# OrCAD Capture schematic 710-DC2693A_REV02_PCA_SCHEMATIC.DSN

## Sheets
1 LTC5556 - PAGE2: size Custom; note: DUAL PROGRAMMABLE GAIN MIXER
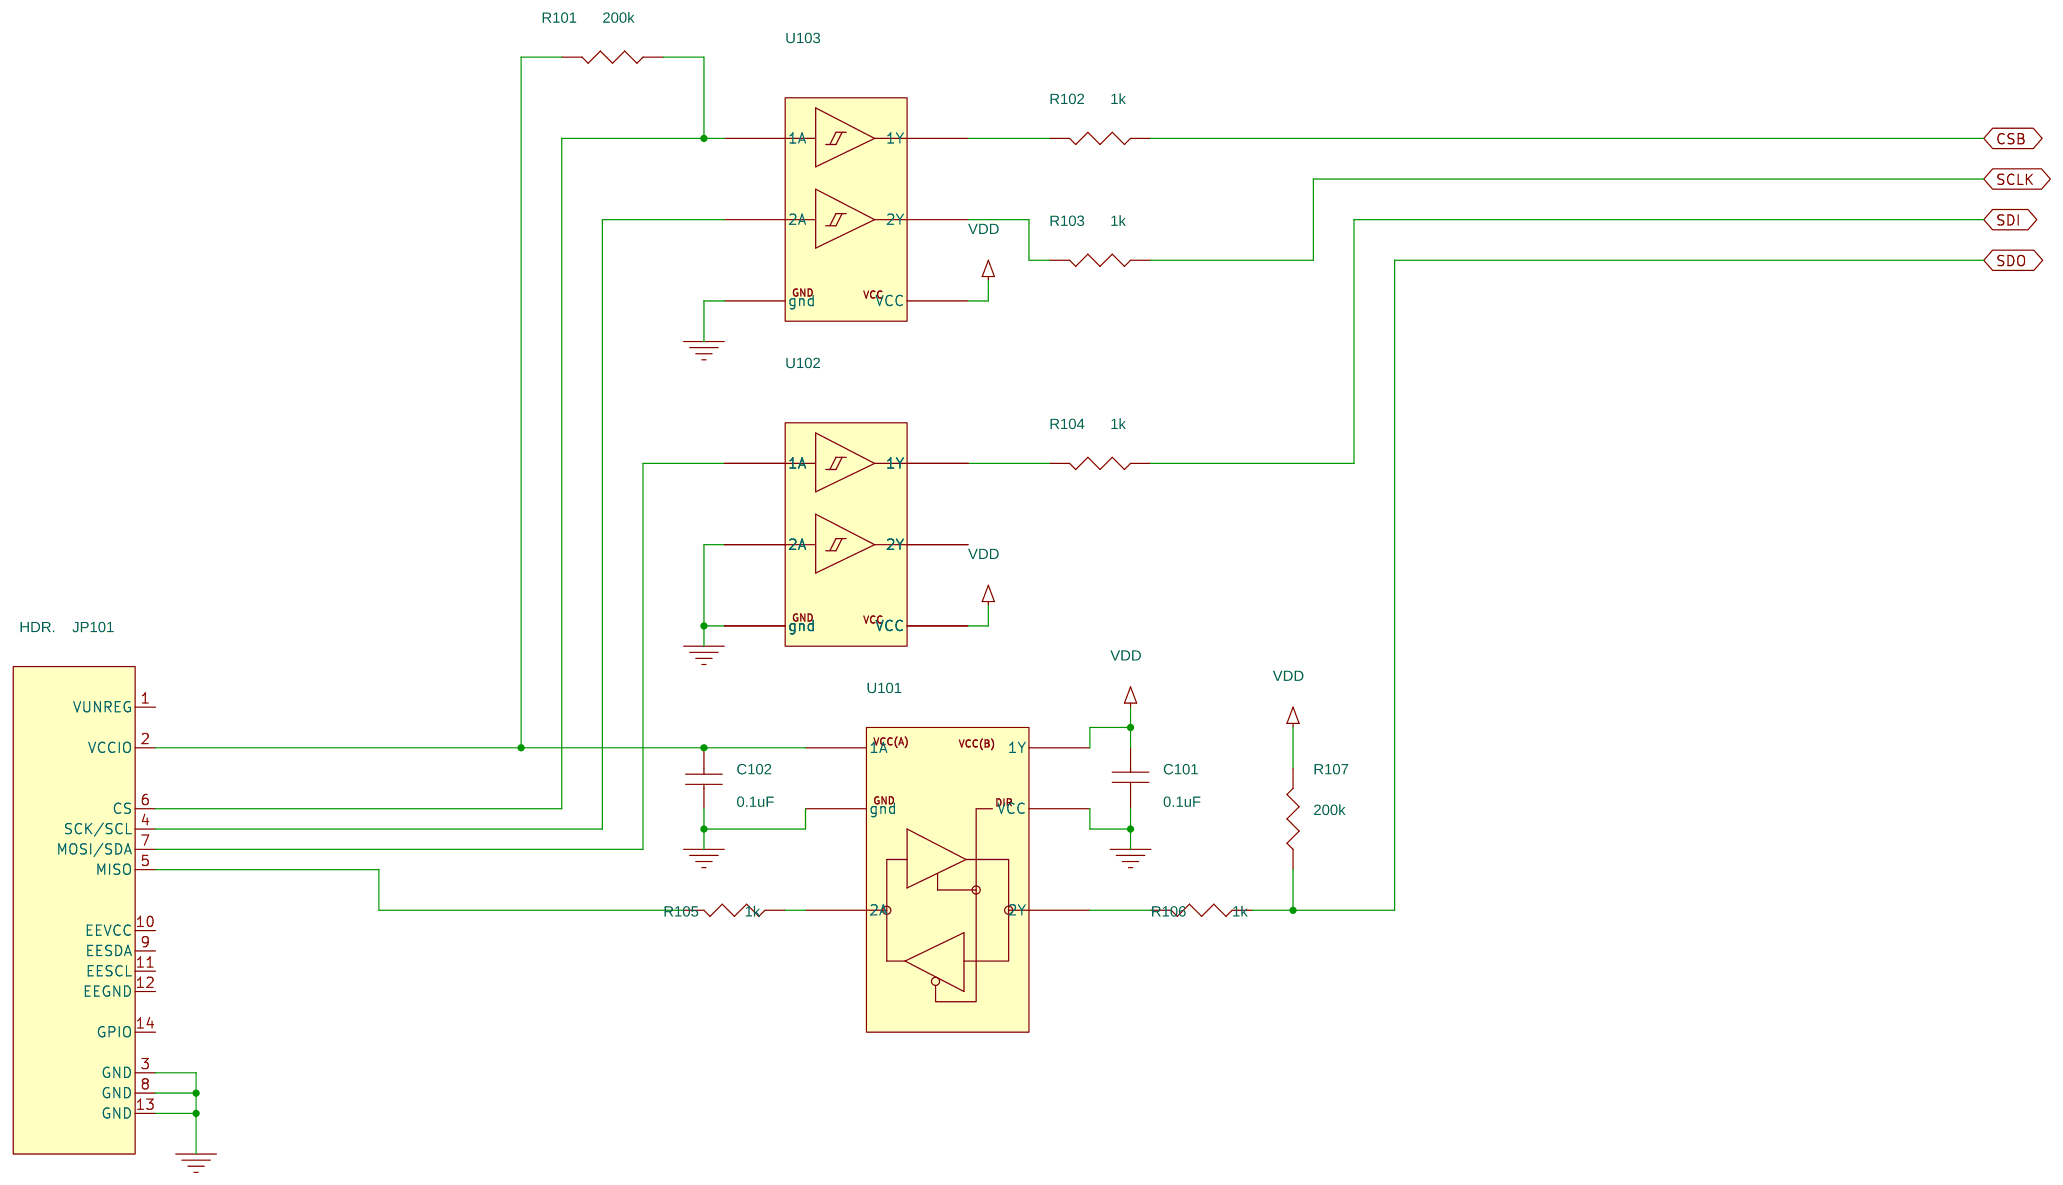
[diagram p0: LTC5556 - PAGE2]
2 LTC5556 - PAGE 1: size Custom
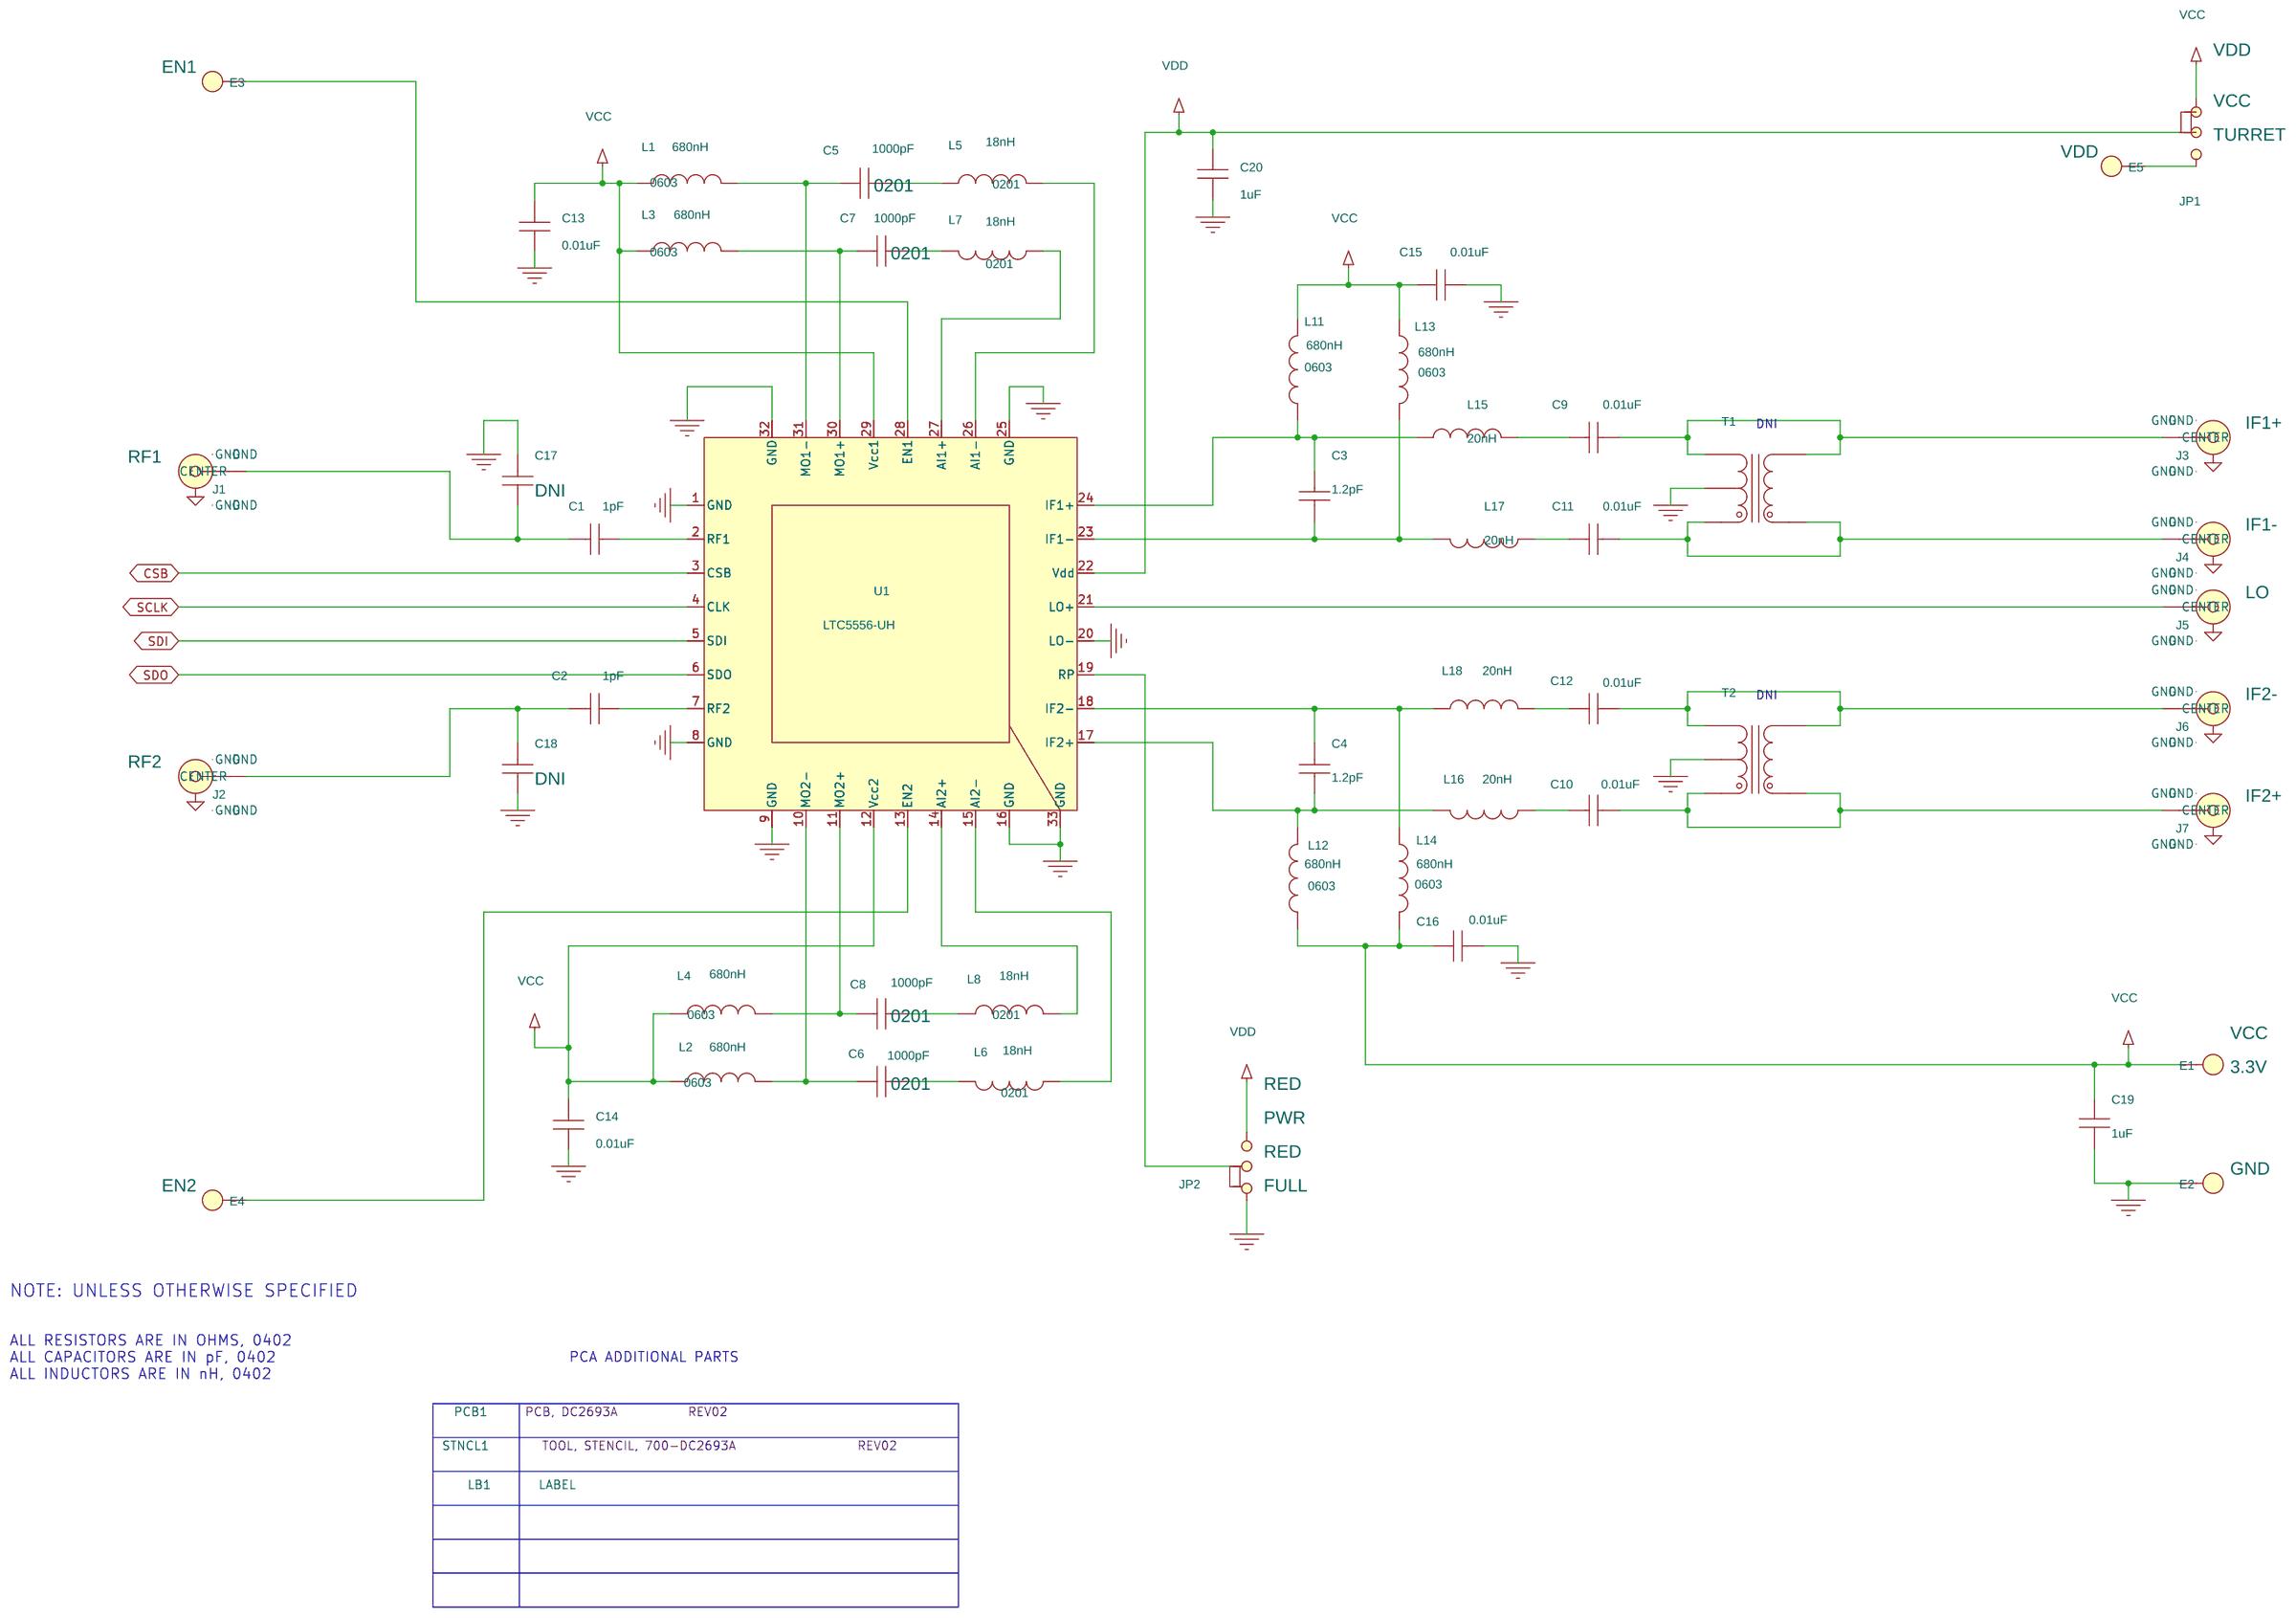
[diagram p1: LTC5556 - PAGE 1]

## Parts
sheet LTC5556 - PAGE2
C101  0.1uF  [CC0402N]
C102  0.1uF  [CC0402N]
JP101  HDR.  [HD2X7-079-MOLEX]
R101  200k  [CR0402N]
R102  1k  [CR0402N]
R103  1k  [CR0402N]
R104  1k  [CR0402N]
R105  1k  [CR0402N]
R106  1k  [CR0402N]
R107  200k  [CR0402N]
U101  74LVC1T45GW  [SOT363-6N]
U102  NC7WZ17P6X  [SC-70(6LEAD)\VISHAY]
U103  NC7WZ17P6X  [SC-70(6LEAD)\VISHAY]
sheet LTC5556 - PAGE 1
C1  1pF  [CC0402N]
C2  1pF  [CC0402N]
C3  1.2pF  [CC0402N]
C4  1.2pF  [CC0402N]
C5  1000pF  [CC0201N]
C6  1000pF  [CC0201N]
C7  1000pF  [CC0201N]
C8  1000pF  [CC0201N]
C9  0.01uF  [CC0402N]
C10  0.01uF  [CC0402N]
C11  0.01uF  [CC0402N]
C12  0.01uF  [CC0402N]
C13  0.01uF  [CC0402N]
C14  0.01uF  [CC0402N]
C15  0.01uF  [CC0402N]
C16  0.01uF  [CC0402N]
C17  OPT  [CC0402N]
C18  OPT  [CC0402N]
C19  1uF  [CC0603N]
C20  1uF  [CC0603N]
E1  TEST POINT  [MILLMAX2308]
E2  TEST POINT  [MILLMAX2308]
E3  TEST POINT  [MILLMAX2308]
E4  TEST POINT  [MILLMAX2308]
E5  TEST POINT  [MILLMAX2308]
J1  SMA  [EMERSON_142-0701-851]
J2  SMA  [EMERSON_142-0701-851]
J3  SMA  [EMERSON_142-0701-851]
J4  SMA  [EMERSON_142-0701-851]
J5  SMA  [EMERSON_142-0701-851]
J6  SMA  [EMERSON_142-0701-851]
J7  SMA  [EMERSON_142-0701-851]
JP1  HDR.  [HD1X3-079]
JP2  HDR.  [HD1X3-079]
L1  680nH  [COILCRAFT-0603CS]
L2  680nH  [COILCRAFT-0603CS]
L3  680nH  [COILCRAFT-0603CS]
L4  680nH  [COILCRAFT-0603CS]
L5  18nH  [IND0201N]
L6  18nH  [IND0201N]
L7  18nH  [IND0201N]
L8  18nH  [IND0201N]
L11  680nH  [COILCRAFT-0603CS]
L12  680nH  [COILCRAFT-0603CS]
L13  680nH  [COILCRAFT-0603CS]
L14  680nH  [COILCRAFT-0603CS]
L15  20nH  [IND0402N]
L16  20nH  [IND0402N]
L17  20nH  [IND0402N]
L18  20nH  [IND0402N]
LB1  LABEL  [895-0154_REV01]
PCB1  PCB, DC2693A
STNCL1  TOOL, STENCIL, 700-DC2693A
T1  TRANS-TC4-1W-7ALN+  [TRANS-TC4-1W-7ALN]
T2  TRANS-TC4-1W-7ALN+  [TRANS-TC4-1W-7ALN]
U1  LTC5556-UH  [LTC-QFN-32-1693]
XJP1  SHUNT
XJP2  SHUNT

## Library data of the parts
C101 C102 = CAP: CAP.,0.1uF,X7R,50V,10%,0402; CLASS: DISCRETE; Dielectric Type: X7R; FPLIST: CC0402N,CC0402L,CC0402M; Manufacturer: MURATA; Manufacturer PN: GRM155R71H104KE14D; PART_NUMBER: 150-3240; Package Size: 0402; Package Type: SMD; Rated Voltage: 50V; Tolerance: 10%
JP101 = CONN_2X7_.079_MOLEX_RIBBON_A: CONN.,HDR.,MALE,2x7,2mm,THT, VERT,SHROUDED; CLASS: IO; Manufacturer: MOLEX; Manufacturer PN: 87831-1420; PART_NUMBER: 250-0403
R101 R107 = RES: RES.,200k OHMS,1%,1/16W,0402; CLASS: DISCRETE; FPLIST: CR0402N,CR0402L,CR0402M; Manufacturer: PANASONIC; Manufacturer PN: ERJ2RKF2003X; PART_NUMBER: 100-0329; Package Size: 0402; Rated Power: 1/16W; Temperature Coefficient: 100ppm/C; Tolerance: 1%
R102-R106 = RES: RES.,1k OHM,1%,1/16W,0402; CLASS: DISCRETE; FPLIST: CR0402N,CR0402L,CR0402M; Manufacturer: VISHAY; Manufacturer PN: CRCW04021K00FKED; PART_NUMBER: 100-2456; Package Size: 0402; Rated Power: 1/16W; Temperature Coefficient: 100ppm/C; Tolerance: 1%
U101 = 74LVC1T45_v2: IC,Dual Supply Transceiver,SOT363-6 (SC-88),Single Bit, 3-State Outputs; CLASS: IC; Manufacturer: NEXPERIA; Manufacturer PN: 74LVC1T45GW,125; PART_NUMBER: 280-8080; Package Type: SOT363-6 (SC-88)
U102 U103 = NC7WZ17: IC,TinyLogic UHS Dual Buffer,SC70-6; CLASS: IC; Manufacturer: FAIRCHILD SEMI.; PART_NUMBER: 280-0294; Package Type: SC70-6
C1 C2 = CAP: CAP.,1pF,C0G,50V,+/-0.05pF,0402,High Q; CLASS: DISCRETE; Dielectric Type: C0G; FPLIST: CC0402N,CC0402L,CC0402M; Manufacturer: MURATA; Manufacturer PN: GJM1555C1H1R0WB01D; PART_NUMBER: 150-2023; Package Size: 0402; Rated Voltage: 50V; Tolerance: +/-0.05pF; UserField01: High Q
C3 C4 = CAP: CAP.,1.2pF,C0G,50V,+/-0.05pF,0402,HIGH Q; CLASS: DISCRETE; Dielectric Type: C0G; FPLIST: CC0402N,CC0402L,CC0402M; Manufacturer: MURATA; Manufacturer PN: GJM1555C1H1R2WB01D; PART_NUMBER: 150-2024; Package Size: 0402; Rated Voltage: 50V; Tolerance: +/-0.05pF; UserField01: High Q
C5-C8 = CAP: CAP.,1000pF,X7R,50V,10%,0201; CLASS: DISCRETE; Dielectric Type: X7R; FPLIST: CC0201N,CC0201L,CC0201M; Manufacturer: MURATA; Manufacturer PN: GRM033R71H102KA12D; PART_NUMBER: 150-2256; Package Size: 0201; Rated Voltage: 50V; Tolerance: 10%
C9-C16 = CAP: CAP.,0.01uF,X7R,50V,10%,0402; CLASS: DISCRETE; Dielectric Type: X7R; FPLIST: CC0402N,CC0402L,CC0402M; Manufacturer: KEMET; Manufacturer PN: C0402C103K5RAC7867; PART_NUMBER: 150-0041; Package Size: 0402; Rated Voltage: 50V; Tolerance: 10%
C17 C18 = CAP: CAP., OPTION, 0402; 1: DNI; CLASS: DISCRETE; FPLIST: CC0402N,CC0402L,CC0402M; PART_NUMBER: 150-3148; Package Size: 0402; Package Type: SMD
C19 C20 = CAP: CAP.,1uF,X7R,16V,10%,0603; CLASS: DISCRETE; Dielectric Type: X7R; FPLIST: CC0603N,CC0603L,CC0603M; Manufacturer: MURATA; Manufacturer PN: GRM188R71C105KA12D; PART_NUMBER: 150-0179; Package Size: 0603; Rated Voltage: 16V; Tolerance: 10%
E1 = TEST_POINT_.156_MILL-MAX_2308: TEST POINT,TURRET,0.064",MTG. HOLE; 1: VCC; 2: 3.3V; CLASS: IO; Manufacturer: MILL-MAX; Manufacturer PN: 2308-2-00-80-00-00-07-0; PART_NUMBER: 260-0004
E2 = TEST_POINT_.156_MILL-MAX_2308: TEST POINT,TURRET,0.064",MTG. HOLE; 1: GND; CLASS: IO; Manufacturer: MILL-MAX; Manufacturer PN: 2308-2-00-80-00-00-07-0; PART_NUMBER: 260-0004
E3 = TEST_POINT_.156_MILL-MAX_2308: TEST POINT,TURRET,0.064",MTG. HOLE; 1: EN1; CLASS: IO; Manufacturer: MILL-MAX; Manufacturer PN: 2308-2-00-80-00-00-07-0; PART_NUMBER: 260-0004
E4 = TEST_POINT_.156_MILL-MAX_2308: TEST POINT,TURRET,0.064",MTG. HOLE; 1: EN2; CLASS: IO; Manufacturer: MILL-MAX; Manufacturer PN: 2308-2-00-80-00-00-07-0; PART_NUMBER: 260-0004
E5 = TEST_POINT_.156_MILL-MAX_2308: TEST POINT,TURRET,0.064",MTG. HOLE; 1: VDD; CLASS: IO; Manufacturer: MILL-MAX; Manufacturer PN: 2308-2-00-80-00-00-07-0; PART_NUMBER: 260-0004
J1 = CONN_SMA_5PIN: CONN.,SMA,JACK, RCPT,END LAUNCH, STR,50 OHMS; 1: RF1; CLASS: IO; FPLIST: EMERSON_142-0701-851,SMA-CINCH-142-0761-881_142-0701-851; Manufacturer: CINCH/ BEL; Manufacturer PN: 142-0701-851; PART_NUMBER: 250-0446
J2 = CONN_SMA_5PIN: CONN.,SMA,JACK, RCPT,END LAUNCH, STR,50 OHMS; 1: RF2; CLASS: IO; FPLIST: EMERSON_142-0701-851,SMA-CINCH-142-0761-881_142-0701-851; Manufacturer: CINCH/ BEL; Manufacturer PN: 142-0701-851; PART_NUMBER: 250-0446
J3 = CONN_SMA_5PIN: CONN.,SMA,JACK, RCPT,END LAUNCH, STR,50 OHMS; 1: IF1+; CLASS: IO; FPLIST: EMERSON_142-0701-851,SMA-CINCH-142-0761-881_142-0701-851; Manufacturer: CINCH/ BEL; Manufacturer PN: 142-0701-851; PART_NUMBER: 250-0446
J4 = CONN_SMA_5PIN: CONN.,SMA,JACK, RCPT,END LAUNCH, STR,50 OHMS; 1: IF1-; CLASS: IO; FPLIST: EMERSON_142-0701-851,SMA-CINCH-142-0761-881_142-0701-851; Manufacturer: CINCH/ BEL; Manufacturer PN: 142-0701-851; PART_NUMBER: 250-0446
J5 = CONN_SMA_5PIN: CONN.,SMA,JACK, RCPT,END LAUNCH, STR,50 OHMS; 1: LO; CLASS: IO; FPLIST: EMERSON_142-0701-851,SMA-CINCH-142-0761-881_142-0701-851; Manufacturer: CINCH/ BEL; Manufacturer PN: 142-0701-851; PART_NUMBER: 250-0446
J6 = CONN_SMA_5PIN: CONN.,SMA,JACK, RCPT,END LAUNCH, STR,50 OHMS; 1: IF2-; CLASS: IO; FPLIST: EMERSON_142-0701-851,SMA-CINCH-142-0761-881_142-0701-851; Manufacturer: CINCH/ BEL; Manufacturer PN: 142-0701-851; PART_NUMBER: 250-0446
J7 = CONN_SMA_5PIN: CONN.,SMA,JACK, RCPT,END LAUNCH, STR,50 OHMS; 1: IF2+; CLASS: IO; FPLIST: EMERSON_142-0701-851,SMA-CINCH-142-0761-881_142-0701-851; Manufacturer: CINCH/ BEL; Manufacturer PN: 142-0701-851; PART_NUMBER: 250-0446
JP1 = HDR3X1_A: CONN.,HDR.,MALE,1x3,2mm,THT, STR; 1: VDD; 2: VCC; 3: TURRET; CLASS: IO; FPLIST: JP3X1/079,HD1X3-079; Manufacturer: SAMTEC; Manufacturer PN: TMM-103-02-L-S; PART_NUMBER: 250-0422
JP2 = HDR3X1_A: CONN.,HDR.,MALE,1x3,2mm,THT, STR; 1: RED; 2: PWR; 3: RED; 4: FULL; CLASS: IO; FPLIST: JP3X1/079,HD1X3-079; Manufacturer: SAMTEC; Manufacturer PN: TMM-103-02-L-S; PART_NUMBER: 250-0422
L1-L4 L11-L14 = IND: IND.,680nH,RF, FERRITE,5%,0603; CLASS: DISCRETE; Manufacturer: COILCRAFT; Manufacturer PN: 0603AF-681XJEU; PART_NUMBER: 200-0286; Package Size: 0603; Tolerance: 5%
L5-L8 = IND: IND.,18nH,FILM,3%,0201,HIGH Q; CLASS: DISCRETE; Manufacturer: MURATA; Manufacturer PN: LQP03HQ18NH02D; PART_NUMBER: 200-0534; Package Size: 0201; Tolerance: 3%
L15-L18 = IND: IND.,20nH,CER.,2%,0402,HIGH Q; CLASS: DISCRETE; FPLIST: IND0402N,IND0402L,IND0402M; Manufacturer: COILCRAFT; Manufacturer PN: 0402HP-20NXGLU; PART_NUMBER: 200-0536; Package Size: 0402; Tolerance: 2%
LB1 = BLANK_LABEL: LABEL SPEC, DEMO BOARD SERIAL NUMBER; Manufacturer: BRADY; Manufacturer PN: THT-96-717-10; PART_NUMBER: 895-0154
PCB1 = BLANK_PCB_PART: BOM Notes: REV02; CLASS: DISCRETE; Manufacturer: ALLTEK CIRCUITS INC.; Manufacturer PN: 600-DC2693A; PART_NUMBER: 600-DC2693A
STNCL1 = BLANK_STENCIL_PART: BOM Notes: REV02; CLASS: DISCRETE; Manufacturer: LINEAR TECH.; Manufacturer PN: 830-DC2693A; PART_NUMBER: 830-DC2693A
T1 T2 = TRANS-TC4-1W-7ALN+: XFMR,RF,CASE STYLE: AT224-1, 5 to 500 MHz; BOM Notes: NO STUFF; CLASS: DISCRETE; Manufacturer: MINI-CIRCUITS; Manufacturer PN: TC4-1W-7ALN+; PART_NUMBER: 410-0101
U1 = LTC5556-UH: IC,Dual PGM Gain Downcvrtg Mixer,QFN-32,3GHz to 7GHz Wideband IF; CLASS: IC; Manufacturer: LINEAR TECH.; Manufacturer PN: LTC5556IUH#PBF; PART_NUMBER: LTC5556IUH#PBF; Package Type: QFN-32
XJP1 XJP2 = SHUNT_2MM_B: CONN.,SHUNT,FEMALE,2-POS,2mm; CLASS: IO; Manufacturer: SAMTEC; Manufacturer PN: 2SN-BK-G; PART_NUMBER: 250-0419

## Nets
GND: C13.1 C14.1 C15.2 C16.2 C17.2 C18.1 C19.2 C20.2 C101.2 C102.1 E2.1(A) J1.2(GND) J1.3(GND) J1.4(GND) J1.5(GND) J2.2(GND) J2.3(GND) J2.4(GND) J2.5(GND) J3.2(GND) J3.3(GND) J3.4(GND) J3.5(GND) J4.2(GND) J4.3(GND) J4.4(GND) J4.5(GND) J5.2(GND) J5.3(GND) J5.4(GND) J5.5(GND) J6.2(GND) J6.3(GND) J6.4(GND) J6.5(GND) J7.2(GND) J7.3(GND) J7.4(GND) J7.5(GND) JP2.3 JP101.3(GND) JP101.8(GND) JP101.13(GND) T1.2 T2.2 U1.1(GND) U1.8(GND) U1.9(GND) U1.16(GND) U1.20(LO-) U1.25(GND) U1.32(GND) U1.33(GND) U101.2(gnd) U101.5(VCC) U102.2(gnd) U102.3(2A) U103.2(gnd)
VCC: C13.2 C14.2 C15.1 C16.1 C19.1 E1.1(A) JP1.1 L1.1 L2.1 L3.1 L4.1 L11.2 L12.1 L13.2 L14.1 U1.12(Vcc2) U1.29(Vcc1)
VDD: C20.1 C101.1 JP1.2 JP2.1 R107.1 U1.22(Vdd) U101.6(1Y) U102.5(VCC) U103.5(VCC)
CSB: R102.2 U1.3(CSB)
SCLK: R103.2 U1.4(CLK)
SDI: R104.2 U1.5(SDI)
SDO: R106.2 R107.2 U1.6(SDO)
N40757: J5.1(CENTER) U1.21(LO+)
N40785: C1.1 U1.2(RF1)
N40789: C2.1 U1.7(RF2)
N40837: C11.2 J4.1(CENTER) T1.1 T1.6
N40897: C4.2 L14.2 L18.1 U1.18(IF2-)
N40905: C4.1 L12.2 L16.2 U1.17(IF2+)
N40921: L8.2 U1.14(AI2+)
N40937: L6.1 U1.15(AI2-)
N41001: C3.1 L11.1 L15.1 U1.24(IF1+)
N41009: C3.2 L13.1 L17.2 U1.23(IF1-)
N41021: JP2.2 U1.19(RP)
N41085: C2.2 C18.2 J2.1(CENTER)
N41089: C1.2 C17.1 J1.1(CENTER)
N41133: C10.1 L16.1
N41137: C12.1 L18.2
N41145: C9.1 L15.2
N41321: E3.1(A) U1.28(EN1)
N41361: E4.1(A) U1.13(EN2)
N69900: C6.1 L2.2 U1.10(MO2-)
N69932: C8.1 L4.2 U1.11(MO2+)
N73620: C7.2 L7.1
N73624: C5.2 L5.1
N76667: L5.2 U1.26(AI1-)
N76702: C7.1 L3.2 U1.30(MO1+)
N76710: L7.2 U1.27(AI1+)
N78123: C5.1 L1.2 U1.31(MO1-)
N84915: C6.2 L6.2
N84921: C8.2 L8.1
N130472: C11.1 L17.1
N194638: E5.1(A) JP1.3
N240210: JP101.7(MOSI/SDA) U102.1(1A)
N240314: R103.1 U103.4(2Y)
N240318: C102.2 JP101.2(VCCIO) R101.1 U101.1(1A)
N240462: R105.2 U101.3(2A)
N240502: JP101.6(CS) R101.2 U103.1(1A)
N240570: JP101.4(SCK/SCL) U103.3(2A)
N240766: R106.1 U101.4(2Y)
N240882: R104.1 U102.6(1Y)
N241050: R102.1 U103.6(1Y)
N16714792: C9.2 J3.1(CENTER) T1.3 T1.4
N16715764: C10.2 J7.1(CENTER) T2.1 T2.6
N16715810: C12.2 J6.1(CENTER) T2.3 T2.4
N16779308: JP101.5(MISO) R105.1

Not connected (* = marked no-connect by the designer): JP101 1(VUNREG) 9(EESDA) 10(EEVCC) 11(EESCL) 12(EEGND) 14(GPIO); U102 4(2Y)

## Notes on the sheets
sheet 2
- DNI
- DNI
- NOTE: UNLESS OTHERWISE SPECIFIED
- ALL RESISTORS ARE IN OHMS, 0402
  ALL CAPACITORS ARE IN pF, 0402
  ALL INDUCTORS ARE IN nH, 0402
- PCA ADDITIONAL PARTS
